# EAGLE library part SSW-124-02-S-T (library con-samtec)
THROUGH-HOLE .025" SQ POST SOCKET Source: Samtec SSW.pdf
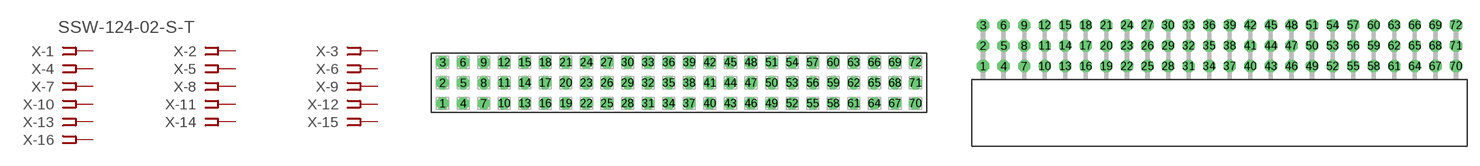
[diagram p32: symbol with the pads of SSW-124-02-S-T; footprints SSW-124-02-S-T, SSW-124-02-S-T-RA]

Designator prefix X; gates -1=FPINV -2=FPIN -3=FPIN -4=FPIN -5=FPIN -6=FPIN -7=FPIN -8=FPIN -9=FPIN -10=FPIN -11=FPIN -12=FPIN -13=FPIN -14=FPIN -15=FPIN -16=FPIN -17=FPIN -18=FPIN -19=FPIN -20=FPIN -21=FPIN -22=FPIN -23=FPIN -24=FPIN -25=FPIN -26=FPIN -27=FPIN -28=FPIN -29=FPIN -30=FPIN -31=FPIN -32=FPIN -33=FPIN -34=FPIN -35=FPIN -36=FPIN -37=FPIN -38=FPIN -39=FPIN -40=FPIN -41=FPIN -42=FPIN -43=FPIN -44=FPIN -45=FPIN -46=FPIN -47=FPIN -48=FPIN -49=FPIN -50=FPIN -51=FPIN -52=FPIN -53=FPIN -54=FPIN -55=FPIN -56=FPIN -57=FPIN -58=FPIN -59=FPIN -60=FPIN -61=FPIN -62=FPIN -63=FPIN -64=FPIN -65=FPIN -66=FPIN -67=FPIN -68=FPIN -69=FPIN -70=FPIN -71=FPIN -72=FPIN

## SSW-124-02-S-T (MPN: SSW-124-02-S-T; OC_FARNELL: unknown; OC_NEWARK: 82P9057)  [SSW-124-02-S-T]
1  -1:1  pas
2  -2:1  pas
3  -3:1  pas
4  -4:1  pas
5  -5:1  pas
6  -6:1  pas
7  -7:1  pas
8  -8:1  pas
9  -9:1  pas
10  -10:1  pas
11  -11:1  pas
12  -12:1  pas
13  -13:1  pas
14  -14:1  pas
15  -15:1  pas
16  -16:1  pas
17  -17:1  pas
18  -18:1  pas
19  -19:1  pas
20  -20:1  pas
21  -21:1  pas
22  -22:1  pas
23  -23:1  pas
24  -24:1  pas
25  -25:1  pas
26  -26:1  pas
27  -27:1  pas
28  -28:1  pas
29  -29:1  pas
30  -30:1  pas
31  -31:1  pas
32  -32:1  pas
33  -33:1  pas
34  -34:1  pas
35  -35:1  pas
36  -36:1  pas
37  -37:1  pas
38  -38:1  pas
39  -39:1  pas
40  -40:1  pas
41  -41:1  pas
42  -42:1  pas
43  -43:1  pas
44  -44:1  pas
45  -45:1  pas
46  -46:1  pas
47  -47:1  pas
48  -48:1  pas
49  -49:1  pas
50  -50:1  pas
51  -51:1  pas
52  -52:1  pas
53  -53:1  pas
54  -54:1  pas
55  -55:1  pas
56  -56:1  pas
57  -57:1  pas
58  -58:1  pas
59  -59:1  pas
60  -60:1  pas
61  -61:1  pas
62  -62:1  pas
63  -63:1  pas
64  -64:1  pas
65  -65:1  pas
66  -66:1  pas
67  -67:1  pas
68  -68:1  pas
69  -69:1  pas
70  -70:1  pas
71  -71:1  pas
72  -72:1  pas

## SSW-124-02-S-TRA (MPN: SSW-124-02-S-T-RA; OC_FARNELL: unknown; OC_NEWARK: 82P9058)  [SSW-124-02-S-T-RA]
Pads as for SSW-124-02-S-T

## Footprint SSW-124-02-S-T (pad centres in mm)
THROUGH-HOLE .025" SQ POST SOCKET Source: Samtec SSW.pdf
drill 1 pad 1.5 octagon: 1 -29.21,-2.54; 2 -29.21,0; 3 -29.21,2.54; 4 -26.67,-2.54; 5 -26.67,0; 6 -26.67,2.54; 7 -24.13,-2.54; 8 -24.13,0; 9 -24.13,2.54; 10 -21.59,-2.54; 11 -21.59,0; 12 -21.59,2.54; 13 -19.05,-2.54; 14 -19.05,0; 15 -19.05,2.54; 16 -16.51,-2.54; 17 -16.51,0; 18 -16.51,2.54; 19 -13.97,-2.54; 20 -13.97,0; 21 -13.97,2.54; 22 -11.43,-2.54; 23 -11.43,0; 24 -11.43,2.54; 25 -8.89,-2.54; 26 -8.89,0; 27 -8.89,2.54; 28 -6.35,-2.54; 29 -6.35,0; 30 -6.35,2.54; 31 -3.81,-2.54; 32 -3.81,0; 33 -3.81,2.54; 34 -1.27,-2.54; 35 -1.27,0; 36 -1.27,2.54; 37 1.27,-2.54; 38 1.27,0; 39 1.27,2.54; 40 3.81,-2.54; 41 3.81,0; 42 3.81,2.54; 43 6.35,-2.54; 44 6.35,0; 45 6.35,2.54; 46 8.89,-2.54; 47 8.89,0; 48 8.89,2.54; 49 11.43,-2.54; 50 11.43,0; 51 11.43,2.54; 52 13.97,-2.54; 53 13.97,0; 54 13.97,2.54; 55 16.51,-2.54; 56 16.51,0; 57 16.51,2.54; 58 19.05,-2.54; 59 19.05,0; 60 19.05,2.54; 61 21.59,-2.54; 62 21.59,0; 63 21.59,2.54; 64 24.13,-2.54; 65 24.13,0; 66 24.13,2.54; 67 26.67,-2.54; 68 26.67,0; 69 26.67,2.54; 70 29.21,-2.54; 71 29.21,0; 72 29.21,2.54

## Footprint SSW-124-02-S-T-RA (pad centres in mm)
THROUGH-HOLE .025" SQ POST SOCKET Source: Samtec SSW.pdf
drill 1 pad 1.5 octagon: 1 -29.21,1.524; 2 -29.21,4.064; 3 -29.21,6.604; 4 -26.67,1.524; 5 -26.67,4.064; 6 -26.67,6.604; 7 -24.13,1.524; 8 -24.13,4.064; 9 -24.13,6.604; 10 -21.59,1.524; 11 -21.59,4.064; 12 -21.59,6.604; 13 -19.05,1.524; 14 -19.05,4.064; 15 -19.05,6.604; 16 -16.51,1.524; 17 -16.51,4.064; 18 -16.51,6.604; 19 -13.97,1.524; 20 -13.97,4.064; 21 -13.97,6.604; 22 -11.43,1.524; 23 -11.43,4.064; 24 -11.43,6.604; 25 -8.89,1.524; 26 -8.89,4.064; 27 -8.89,6.604; 28 -6.35,1.524; 29 -6.35,4.064; 30 -6.35,6.604; 31 -3.81,1.524; 32 -3.81,4.064; 33 -3.81,6.604; 34 -1.27,1.524; 35 -1.27,4.064; 36 -1.27,6.604; 37 1.27,1.524; 38 1.27,4.064; 39 1.27,6.604; 40 3.81,1.524; 41 3.81,4.064; 42 3.81,6.604; 43 6.35,1.524; 44 6.35,4.064; 45 6.35,6.604; 46 8.89,1.524; 47 8.89,4.064; 48 8.89,6.604; 49 11.43,1.524; 50 11.43,4.064; 51 11.43,6.604; 52 13.97,1.524; 53 13.97,4.064; 54 13.97,6.604; 55 16.51,1.524; 56 16.51,4.064; 57 16.51,6.604; 58 19.05,1.524; 59 19.05,4.064; 60 19.05,6.604; 61 21.59,1.524; 62 21.59,4.064; 63 21.59,6.604; 64 24.13,1.524; 65 24.13,4.064; 66 24.13,6.604; 67 26.67,1.524; 68 26.67,4.064; 69 26.67,6.604; 70 29.21,1.524; 71 29.21,4.064; 72 29.21,6.604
